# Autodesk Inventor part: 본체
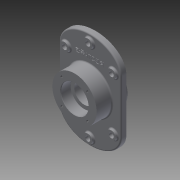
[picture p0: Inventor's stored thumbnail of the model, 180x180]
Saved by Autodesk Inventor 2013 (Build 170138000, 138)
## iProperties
Created: 2015-02
Part Number: 본체
Material: 일반
Document SubType Name: Modeling
Designer: Administrator
Density: 1 g/cm^3
Author: Administrator
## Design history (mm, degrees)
sketch "스케치6" dims "d59" = 50, "d60" = 50
  geometry: L1 (-70, 60)-(70, 60); L2 (70, 60)-(70, -60); L3 (70, -60)-(-70, -60); L4 (-70, -60)-(-70, 60); 5 further points; 2 other entities
  constraints: 8 end point, 3 horizontal, 3 midpoint, 2 parallel, 1 coincident, 1 horizontal alignment, 1 perpendicular, 1 vertical alignment, 8 other
  dimensions: "d29" = 120 distance of L3.end L1.start; "d31" = 140 distance of L2.end L3.end
extrude "돌출4" new body sketch "스케치6" distance "d33" = 12; taper "d34" = 0 deg
node "작업 평면3"
sketch "스케치7"
  geometry: C1 r 50 at (0, 0); 1 further point
  constraints: 1 centre point, 1 coincident
  dimensions: "d36" = 100 diameter of C1
extrude "돌출5" join sketch "스케치7" distance "d37" = 70; taper "d38" = 0 deg
node "작업 평면4"
sketch "스케치8"
  geometry: C1 r 50 at (0, 0) reference; C2 r 22.5 at (0, 0)
  constraints: 1 centre point, 1 coincident
  dimensions: "d40" = 45 diameter of C2
extrude "돌출6" cut sketch "스케치8" distance "d41" = 70; taper "d42" = 0 deg
sketch "스케치9"
  geometry: C1 r 22.5 at (0, 0) reference; C2 r 50 at (0, 0) reference; C3 r 31 at (0, 0)
  constraints: 1 centre point, 1 coincident
  dimensions: "d43" = 62 diameter of C3
extrude "돌출7" cut sketch "스케치9" distance "d44" = 22; taper "d45" = 0 deg
sketch "스케치10"
  geometry: L1 (0, 0)-(28.991, 28.991); L2 (0, 0)-(41, 0); C1 r 50 at (0, 0) reference; 1 further point
  constraints: 4 end point, 1 coincident, 1 equal length, 1 horizontal
  dimensions: "d46" = 41 distance of L1.start L1.end; "d47" = 45 deg angle of L2 L1
hole "구멍2" sketch "스케치10" at (28.991, 28.991) diameter "d48" = 4.917; stored, may be unused: countersink angle "d52" = 90 deg, drill point angle "d54" = 118 deg; dims "d49" = 10, "d50" = 4, "d51" = 2, "d53" = 13
sketch "스케치13"
  geometry: L1 (-70, 60)-(-70, -60) reference; L2 (70, -60)-(70, 60) reference; L3 (-53, 60)-(-53, -60); L4 (53, -60)-(53, 60); C1 r 50 at (0, 0) reference; C2 r 10 at (0, 93); C3 r 10 at (-53, 60); C4 r 10 at (53, 60); 2 further points; 2 other entities
  constraints: 4 end point, 3 centre point, 3 parallel, 2 coincident, 1 horizontal alignment, 1 vertical alignment, 8 other
  dimensions: "d61" = 17 distance between parallel lines of L2 L4; "d62" = 20 diameter of C2; "d63" = 20 diameter of C3; "d64" = 20 diameter of C4
extrude "돌출8" join sketch "스케치13" distance "d65" = 5; taper "d66" = 0 deg
sketch "스케치14"
  geometry: C1 r 10 at (0, 0) reference; C2 r 10 at (-53, -33) reference; C3 r 10 at (53, -33) reference; 1 further point
hole "구멍3" sketch "스케치14" at (0, 0), (-53, -33), (53, -33) diameter "d67" = 11; stored, may be unused: countersink angle "d71" = 90 deg, drill point angle "d73" = 118 deg; dims "d68" = 10, "d69" = 4, "d70" = 2, "d72" = 13
chamfer "모따기1" distance "d74" = 1; stored, may be unused: second distance "d75" = 2, angle "d76" = 45 deg
fillet "모깎기1" dims "d77" = 0.3
fillet "모깎기2" dims "d78" = 3
sketch "스케치15"
  geometry: C1 r 53 at (0, 0) reference; 1 further point
  constraints: 1 vertical alignment, 1 other
  dimensions: "d79" = 65 distance of C1.centre point (0, 65)
feature "엠보싱1" sketch "스케치15" dims "d29" = 120, "d31" = 140, "d59" = 50, "d60" = 50, "d80" = 1, "d81" = 0
node "솔리드2"
pattern_circular "원형 패턴1" dims angle "d56" = 360 deg
mirror "대칭2"
mirror "대칭3"
other parameters: "d35" = 23, "d39" = -35
